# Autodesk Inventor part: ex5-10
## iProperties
Author: E. MOSS
Created: 2001-08
Part Number: ex5-10
Document SubType Name: Modeling
Designer: E. MOSS
Control State: 0
Master: False
Checked Out: False
PropertySet Name: Design Tracking Control
Length Units: 11272
Angle Units: 11279
Time Units: 11290
Mass Units: 11286
Shininess: 3
Angle Display Precision: 2
Document Length Units: 11272
Document Angle Units: 11286
Document Time Units: 11279
Document Mass Units: 11290
Document Length Units Precision: 3
Document Angle Units Precision: 2
Compacted: True
PropertySet Name: _Private Model Information
Density: 0.0
Volumn: 0.0
Area: 0.0
PropertySet Name: Model Information
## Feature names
1. Revolution1
2. Hole2
3. Shell1
4. Loft1
5. Sweep1
6. Coil2
7. Fillet1
8. Chamfer1
9. Keyhole [Extrusion]
